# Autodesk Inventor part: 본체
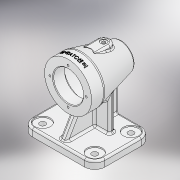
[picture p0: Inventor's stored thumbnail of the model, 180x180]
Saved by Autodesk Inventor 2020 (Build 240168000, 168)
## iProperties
Created: 2024-12
Part Number: 본체
Material: 알루미늄 6061
Document SubType Name: Modeling
Designer: 1강의실14
Mass: 739.149 g
Surface Area: 674.439 cm^2
Volume: 273.759 cm^3
Density: 2.7 g/cm^3
Appearance: 알루미늄 - 평지
Author: 1강의실14
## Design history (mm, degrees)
sketch "스케치1"
  geometry: L1 (37, 28)-(0, 28); L2 (0, 28)-(0, -56); L3 (0, -56)-(37, -56); L4 (37, -56)-(37, 28); L5 (23.5, 28)-(37, 28); L6 (37, 28)-(37, 8); L7 (37, 8)-(21, -56); L8 (21, -56)-(0, -56); L9 (23.5, 28)-(23.5, 10); L10 (23.5, 10)-(32.346, 10); L11 (32.346, 10)-(21.096, -35); L12 (21.096, -35)-(17.5, -35); L13 (17.5, -35)-(17.5, -45); L14 (17.5, -45)-(15.5, -45); L15 (15.5, -45)-(15.5, -48); L16 (15.5, -48)-(0, -48); 1 further point
  constraints: 32 end point, 6 perpendicular, 5 point on line, 4 parallel, 2 horizontal, 1 collinear, 1 vertical
  dimensions: "d0" = 84 distance of L1.end L2.end; "d1" = 74 diameter of L4 L2; "d2" = 56 distance of L2.end point (0, 0); "d14" = 18 distance of L5.start L9.end; "d15" = 20 distance of L1.start L6.end; "d16" = 42 diameter of L7.end L2; "d17" = 5 distance between parallel lines of L7 L11; "d18" = 31 diameter of L15 L2; "d19" = 35 diameter of L13 L2; "d20" = 3 distance of L14.end L15.end; "d21" = 10 distance of L12.end L13.end; "d22" = 45 distance from line of L12 L10.end; "d23" = 47 diameter of L9 L2
revolve "회전1" sketch "스케치1" stored, may be unused: angle "d24" = 90 deg
sketch "스케치2"
  geometry: L1 (-70, 43)-(-82, 43); L2 (-82, 43)-(-82, -46); L3 (-82, -46)-(-70, -46); L4 (-70, -46)-(-70, 43); L5 (-37, 28)-(37, 28) reference; 1 further point
  constraints: 8 end point, 2 parallel, 1 horizontal, 1 perpendicular
  dimensions: "d25" = 12 distance of L3.end L2.end; "d26" = 89 distance of L2.end L1.end; "d27" = 82 distance from line of L2 point (0, 0); "d28" = 15 distance between parallel lines of L5 L1
extrude "돌출1" join sketch "스케치2" stored distance "d29" = 114; taper "d30" = 0 deg
sketch "스케치3"
  geometry: L1 (29, 60)-(85, 60); L2 (85, 60)-(85, 52); L3 (85, 52)-(29, 52); L4 (29, 52)-(29, 60); L5 (0, 89)-(114, 89) reference; 2 further points
  constraints: 8 end point, 2 parallel, 1 horizontal, 1 midpoint, 1 perpendicular, 1 vertical alignment
  dimensions: "d31" = 8 distance of L1.end L2.end; "d32" = 29 distance between parallel lines of L1 L5; "d33" = 56 distance of L1.start L1.end
extrude "돌출2" join sketch "스케치3" stored distance "d34" = 114; taper "d35" = 0 deg
sketch "스케치4"
  geometry: L1 (-37, 28)-(-37, 8) reference; L2 (-37, 16.947)-(-70, 36); L3 (-70, 43)-(-70, -46) reference; L4 (-82, 43)-(-70, 43) reference; 1 further point
  constraints: 2 end point, 2 point on line
  dimensions: "d36" = 60 deg angle of L3 L2; "d37" = 7 distance from line of L4 L2.end
feature "리브1" sketch "스케치4" dims "d38" = 1, "d39" = 10, "d40" = 0, "d41" = 0, "d42" = 1, "d43" = 1
sketch "스케치5"
  geometry: L1 (0, 0)-(114, 0) reference; L2 (52, 0)-(62, 0); L3 (62, 0)-(62, -29); L4 (62, -29)-(52, -29); L5 (52, -29)-(52, 0); 3 further points
  constraints: 8 end point, 2 parallel, 1 horizontal, 1 midpoint, 1 perpendicular, 1 point on line, 1 vertical alignment
  dimensions: "d44" = 10 distance of L3.end L4.end; "d45" = 29 distance of L2.end L3.end
extrude "돌출3" join sketch "스케치5" stored distance "d46" = 114; taper "d47" = 0 deg
sketch "스케치6" dims "d48" = 57
  geometry: 3 further points
  constraints: 2 vertical alignment, 1 coincident, 2 other
hole "구멍1" sketch "스케치6" at (0, 28.5) diameter "d49" = 3.242; stored, may be unused: countersink angle "d53" = 90 deg, drill point angle "d55" = 120 deg; dims "d50" = 8, "d51" = 4, "d52" = 2, "d54" = 10
sketch "스케치7"
  geometry: L1 (0, 89)-(0, 0) reference; L2 (0, 89)-(114, 89) reference; 2 further points
  dimensions: "d60" = 16 distance from line of point (16, 73) L1; "d61" = 16 distance from line of point (16, 73) L2
hole "구멍2" sketch "스케치7" at (16, 73) diameter "d62" = 9; stored, may be unused: countersink angle "d66" = 90 deg, drill point angle "d68" = 120 deg; dims "d63" = 12, "d64" = 24, "d65" = 2, "d67" = 16
sketch "스케치8"
  geometry: L1 (33, 12.616)-(33, -38); L2 (33, -38)-(20.346, -38); L3 (20.346, -38)-(33, 12.616); L4 (21.096, -35)-(32.346, 10) reference; L5 (-82, -34.5)-(-82, -25.5) reference; L6 (-37, 28)-(37, 28) reference; 1 further point
  constraints: 6 end point, 2 collinear, 1 perpendicular, 1 vertical
  dimensions: "d75" = 115 distance between parallel lines of L5 L1; "d76" = 66 distance between parallel lines of L6 L2
extrude "돌출4" join sketch "스케치8" stored distance "d77" = 20; taper "d78" = 0 deg
sketch "스케치9"
  geometry: L1 (47, -66)-(-27, -66) reference; L2 (0, -35.928)-(0, 0) reference; L3 (20, 0)-(0, 0) reference; L4 (20, 0)-(20, -35.928) reference; C1 r 10 at (10, -10); 4 further points
  constraints: 1 centre point, 1 vertical alignment
  dimensions: "d79" = 20 diameter of C1; "d80" = 56 distance from line of L1 C1.centre
extrude "돌출5" cut sketch "스케치9" stored distance "d81" = 10.75; taper "d82" = 0 deg
sketch "스케치10"
  geometry: A1 r 10 centre (0, 0) between (10, 0) and (-10, 0) reference; 2 further points
  constraints: 1 coincident
hole "구멍3" sketch "스케치10" at (0, 0) diameter "d83" = 5.1881; stored, may be unused: countersink angle "d87" = 90 deg, drill point angle "d89" = 120 deg; dims "d84" = 12, "d85" = 10, "d86" = 1, "d88" = 16
node "작업 평면2"
sketch "스케치11"
  geometry: L1 (-37, 10)-(37, 10) reference; 2 further points
  constraints: 1 vertical alignment, 1 other
  dimensions: "d90" = 9 distance from line of L1 point (0, 1)
feature "엠보싱1" sketch "스케치11" dims "d0" = 84, "d1" = 74, "d2" = 56, "d14" = 18, "d15" = 20, "d16" = 42, "d17" = 5, "d18" = 31, "d19" = 35, "d20" = 3, "d21" = 10, "d22" = 45, "d23" = 47, "d25" = 12, "d26" = 89, "d27" = 82, "d28" = 15, "d91" = 0.5, "d92" = 0
chamfer "모따기1" distance "d93" = 1; stored, may be unused: second distance "d94" = 2, angle "d95" = 45 deg
fillet "모깎기1" dims "d96" = 16, "d97" = 5, "d98" = 0.3
fillet "모깎기2" dims "d99" = 3
fillet "모깎기3" dims "d100" = 3
fillet "모깎기4" dims "d101" = 10
node "솔리드1"
pattern_circular "원형 패턴1" dims angle "d57" = 360 deg
pattern_linear "직사각형 패턴1" dims "d71" = 57, "d74" = 82
feature "A9D066F2-1C7D-4E18-AEED-F7BC21143FA4" dims "d62" = 9, "d63" = 12, "d64" = 24, "d65" = 2, "d66" = 90 deg, "d67" = 16, "d68" = 120 deg
